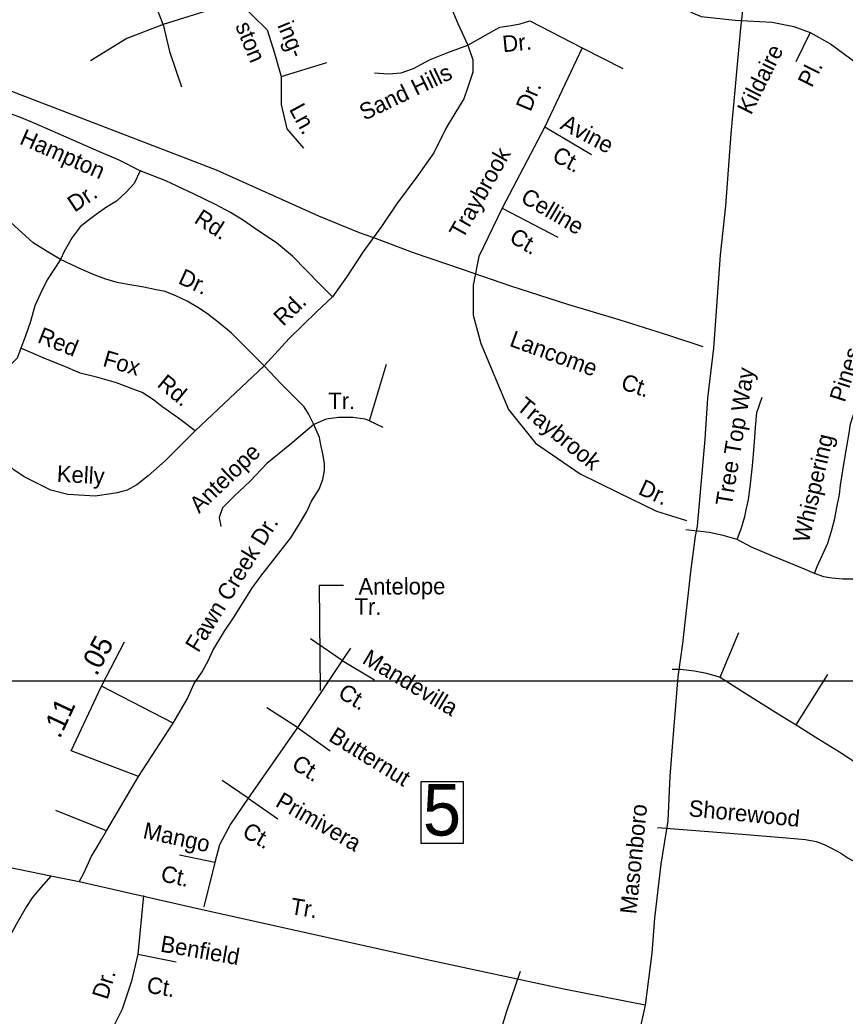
# Model space of a CAD drawing. Extents: x 1945482 to 2853149, y 66427 to 1015778.
# Drawn here: x 2341398 to 2344687, y 153265 to 157233 of the extents above; entities that cross this region are included whole.
import ezdxf

# ---------------------------------------------------------------- set-up
doc = ezdxf.new("R2010")
doc.units = 0
for name, color, linetype in [('Old_Level_10', 7, 'Continuous'), ('Old_Level_11', 7, 'Continuous'), ('Old_Level_31', 7, 'Continuous'), ('Old_Level_32', 7, 'Continuous'), ('Old_Level_35', 7, 'Continuous'), ('Old_Level_63', 7, 'Continuous')]:
    doc.layers.add(name, color=color, linetype=linetype)

msp = doc.modelspace()

# ---------------------------------------------------------------- linework, layer by layer
at = {"layer": 'Old_Level_10'}
msp.add_lwpolyline([(2342688.5, 154979.8), (2342591.2, 154979.8), (2342594.8, 154561.7)], dxfattribs=at)
at = {"layer": 'Old_Level_31'}
msp.add_lwpolyline([(2342998.1, 154198.8), (2343164.4, 154198.8), (2343164.4, 153952.9), (2342998.1, 153952.9)], close=True, dxfattribs=at)
at = {"layer": 'Old_Level_32'}
for points in [[(2344309.2, 157539), (2344270.7, 157199.7), (2344232.2, 156778.6), (2344210.6, 156492.3), (2344188.9, 156295.9), (2344162.5, 155925.4), (2344138.4, 155725.7), (2344128.4, 155563.2), (2344098, 155216.7), (2344089.9, 155176.6), (2344070.7, 155035.1), (2344038.6, 154749.6), (2344020.6, 154616.4), (2344006.2, 154436.7), (2343988.1, 154220.1), (2343980.9, 154043.3), (2343952.1, 153870), (2343926.8, 153655.1), (2343917.2, 153515.5), (2343889.6, 153308.6)], [(2343889.6, 153308.6), (2343565.7, 153372.8), (2343039.8, 153485.1), (2342113.2, 153690.4), (2341634.3, 153799.4), (2341521.8, 153823), (2341308, 153866.4), (2341098.2, 153910.3), (2341029.7, 153923.7), (2340963, 153934.8), (2340619.4, 154012.2), (2340359.7, 154028.2), (2340178.6, 154039.4), (2339839.3, 154055.5), (2339301.6, 154074.7), (2339229.5, 154077.9), (2338943.1, 154093.4), (2338589.8, 154113)], [(2343889.6, 153308.6), (2343857.9, 153165.8), (2343816.2, 153047.1), (2343752.1, 152904.3), (2343535, 152505.6), (2343386.2, 152213.6), (2343300.4, 152065.3), (2343196.1, 151853.5), (2343166, 151804.5), (2343107.6, 151697.1), (2343075.6, 151640.6), (2343054.9, 151582.2), (2343026.7, 151531.3), (2343013.5, 151508.7), (2343013.5, 151503.1), (2343009.7, 151489.9), (2343006, 151471.1), (2342996.6, 151422.1), (2342992.8, 151382.5), (2342995.1, 151254.4)]]:
    msp.add_lwpolyline(points, dxfattribs=at)
at = {"layer": 'Old_Level_35'}
for p, q in [((2342372, 155854.4), (2342096.8, 155596.6)), ((2342791.9, 155635.5), (2342844.8, 155610.8)), ((2344189.4, 154615), (2344262.9, 154792.6)), ((2341722.8, 154579.7), (2341814.5, 154756.2)), ((2344492.3, 154424.9), (2344617.7, 154625.8)), ((2342008.6, 154431.4), (2341722.8, 154579.7)), ((2341871, 154219.5), (2342008.6, 154431.4)), ((2341743, 154003), (2341871, 154219.5)), ((2341743, 154003), (2341541.1, 154083.6))]:
    msp.add_line(p, q, dxfattribs=at)
for points in [[(2343264.7, 158245), (2343247, 158181.4), (2343232.9, 158114.3), (2343116.5, 157725.9), (2343091.8, 157658.8), (2343074.1, 157612.9), (2343053, 157545.8), (2343053, 157499.9), (2343060, 157461), (2343070.6, 157422.2), (2343088.2, 157369.2), (2343112.9, 157291.6), (2343143.4, 157218.8), (2343183.5, 157132.7)], [(2343383.1, 157603.8), (2344079.4, 157261.5), (2344112.7, 157246.4), (2344248.6, 157231.3)], [(2340375.1, 157330.2), (2342180.8, 156636.2), (2342588.1, 156452.2), (2342750.9, 156386.7), (2342807.2, 156365.9)], [(2342135.4, 157266.2), (2341968.6, 157214.2), (2341924.1, 157332.9)], [(2342257.7, 157321.8), (2342324.4, 157252.1), (2342383.7, 157192.7), (2342413.3, 157100), (2342439.3, 157007.3), (2342439.3, 156896), (2342461.5, 156799.6), (2342528.2, 156721.7)], [(2341968.6, 157214.2), (2341824, 157159.4), (2341679.5, 157070.3)], [(2341968.6, 157214.2), (2341994.5, 157107.4), (2342042.7, 156966.5)], [(2343183.5, 157132.7), (2343254.1, 157171.5), (2343310.5, 157203.3), (2343356.4, 157210.3), (2343391.7, 157217.4)], [(2343391.7, 157217.4), (2343431.1, 157229.1), (2343638.7, 157121.5), (2343801.7, 157039.9)], [(2344248.6, 157231.3), (2344396.7, 157223.7), (2344482.2, 157206.5), (2344547.2, 157182.6), (2344629.4, 157138.1), (2344735.4, 157059.3)], [(2344547.2, 157182.6), (2344491.1, 157066.2)], [(2343183.5, 157132.7), (2343202.9, 157074.4), (2343203.4, 157024.4), (2343181.7, 156961.4), (2343167.6, 156919), (2343135.9, 156866.1), (2343097.1, 156802.5), (2343047.7, 156703.6), (2342980.6, 156608.3), (2342899.5, 156498.8), (2342839.5, 156410.5), (2342807.2, 156365.9), (2342765.4, 156308.1), (2342700.3, 156207.5), (2342643.7, 156129.8)], [(2342811.3, 157021.4), (2342867.7, 157017.9), (2342917.1, 157021.4), (2342966.5, 157039.1), (2343030, 157074.4), (2343104.1, 157102.6), (2343183.5, 157132.7)], [(2343638.7, 157121.5), (2343490.4, 156806.3), (2343319.9, 156483.6), (2343227.3, 156290.7), (2343205, 156175.7), (2343205, 156057.1), (2343234.7, 155944.3), (2343345.9, 155681), (2343453.3, 155547.5), (2343631.3, 155425.1), (2343783.2, 155350.9), (2343935.2, 155276.7)], [(2342439.3, 157007.3), (2342620.9, 157062.9)], [(2341878, 156631.2), (2341793.3, 156673.6), (2341712.2, 156708.9), (2341528.7, 156790.1), (2341454.6, 156821.9), (2341398, 156845.9), (2341352.3, 156860.8), (2341313.5, 156867.8), (2341267.6, 156871.4), (2341228.8, 156871.4), (2341158.2, 156853.7)], [(2343490.4, 156806.3), (2343675.7, 156697.2)], [(2341878, 156631.2), (2341853.3, 156581.8), (2341821.6, 156546.5), (2341782.8, 156511.2), (2341743.9, 156486.5), (2341701.6, 156458.2), (2341669.8, 156433.5), (2341638.1, 156408.8), (2341606.3, 156366.4), (2341574.6, 156309.9), (2341560.5, 156278.1)], [(2342643.7, 156129.8), (2342594.3, 156179.3), (2342484.9, 156292.3), (2342421.4, 156345.2), (2342350.8, 156391.1), (2342284.8, 156435.9), (2342237.9, 156465.3), (2342177.9, 156497.1), (2342093.2, 156539.4), (2341980.3, 156592.4), (2341878, 156631.2)], [(2343319.9, 156483.6), (2343542.3, 156367.1)], [(2341560.5, 156278.1), (2341507.5, 156309.9), (2341451.1, 156345.2), (2341377, 156412.3), (2341324.1, 156461.7)], [(2342807.2, 156365.9), (2342966.1, 156306.9), (2343164.7, 156239), (2343353.4, 156174.2), (2343580.4, 156101.2), (2343785, 156039.4), (2343987.5, 155975.2), (2344119.5, 155932.5)], [(2341560.5, 156278.1), (2341507.5, 156196.9), (2341479.3, 156140.4), (2341458.1, 156094.5), (2341440.5, 156031), (2341419.3, 155970.9), (2341401.7, 155925)], [(2342372, 155854.4), (2342294.4, 155932.1), (2342241.4, 155985), (2342195.6, 156023.9), (2342146.2, 156062.7), (2342107.4, 156087.5), (2342065, 156112.2), (2342019.2, 156133.4), (2341976.8, 156151), (2341941.5, 156158.1), (2341892.1, 156168.7), (2341828.6, 156179.3), (2341786.3, 156186.3), (2341740.4, 156200.4), (2341694.5, 156218.1), (2341645.1, 156239.3), (2341560.5, 156278.1)], [(2342643.7, 156129.8), (2342580.2, 156069.8), (2342470.8, 155963.9), (2342372, 155854.4)], [(2341401.7, 155925), (2341387.6, 155886.2), (2341352.3, 155850.9), (2341331.1, 155826.1), (2341292.3, 155773.2), (2341250, 155730.8), (2341207.6, 155688.4), (2341165.3, 155635.5)], [(2342096.8, 155596.6), (2342026.2, 155649.6), (2341963.3, 155693.6), (2341930.9, 155720.2), (2341885.1, 155748.5), (2341839.2, 155766.1), (2341782.8, 155787.3), (2341708.7, 155808.5), (2341638.1, 155826.1), (2341571.1, 155854.4), (2341500.5, 155882.6), (2341401.7, 155925)], [(2342569.6, 155621.3), (2342548.4, 155663.7), (2342530.8, 155692), (2342439, 155783.8), (2342372, 155854.4)], [(2342791.9, 155635.5), (2342858.9, 155861.5)], [(2344564.8, 155028.4), (2344575.6, 155055.3), (2344597.1, 155102), (2344618.6, 155148.6), (2344634.7, 155202.4), (2344645.5, 155247.2), (2344654.4, 155290.3), (2344665.2, 155342.3), (2344668.8, 155379.9), (2344683.1, 155471.4), (2344693.9, 155534.2), (2344702.8, 155586.2), (2344708.2, 155623.9), (2344720.7, 155659.7), (2344733.3, 155695.6), (2344756.6, 155735)], [(2344256.6, 155162.9), (2344274.5, 155209.6), (2344287.1, 155254.4), (2344292.4, 155281.3), (2344301.4, 155322.6), (2344308.6, 155372.8), (2344317.5, 155457.1), (2344324.7, 155534.2), (2344330.1, 155609.5), (2344335.5, 155668.7), (2344357, 155729.7)], [(2342096.8, 155596.6), (2342040.3, 155540.1), (2341976.8, 155476.6), (2341909.8, 155416.5), (2341863.9, 155381.2), (2341825.1, 155360), (2341786.3, 155349.5), (2341743.9, 155342.4), (2341698.1, 155335.3), (2341655.7, 155338.9), (2341588.7, 155342.4), (2341521.7, 155360), (2341465.2, 155388.3), (2341415.8, 155413), (2341373.5, 155441.3), (2341331.1, 155483.6), (2341288.8, 155522.5), (2341239.4, 155571.9), (2341165.3, 155635.5)], [(2342008.6, 154431.4), (2342065, 154526.7), (2342093.2, 154590.3), (2342125, 154636.2), (2342149.7, 154682.1), (2342167.3, 154720.9), (2342213.2, 154798.6), (2342252, 154855.1), (2342322.6, 154968.1), (2342357.9, 155017.5), (2342477.8, 155169.4), (2342513.1, 155225.9), (2342541.3, 155275.3), (2342560.4, 155315.5), (2342590.7, 155363.6), (2342604.9, 155402.4), (2342611.9, 155437.7), (2342611.9, 155466), (2342604.9, 155504.8), (2342597.8, 155540.1), (2342592.2, 155569.9), (2342569.6, 155621.3)], [(2342569.6, 155621.3), (2342474.3, 155540.1), (2342382.6, 155466), (2342315.5, 155395.4), (2342252, 155335.3), (2342206.2, 155289.4), (2342192, 155250.6), (2342199.1, 155215.3)], [(2342791.9, 155635.5), (2342774.2, 155642.5), (2342724.8, 155649.6), (2342668.4, 155649.6), (2342619, 155642.5), (2342569.6, 155621.3)], [(2343935.2, 155276.7), (2344055.3, 155239.4)], [(2344256.6, 155162.9), (2344201, 155179.1), (2344145.5, 155191.6), (2344052, 155202.1)], [(2344564.8, 155028.4), (2344525.4, 155044.6), (2344464.5, 155069.7), (2344392.8, 155100.2), (2344313.9, 155132.4), (2344256.6, 155162.9)], [(2344925, 155030.2), (2344887.4, 155021.3), (2344856.9, 155014.1), (2344813.9, 155008.7), (2344763.7, 155006.9), (2344720.7, 155005.1), (2344677.7, 155005.1), (2344634.7, 155008.7), (2344602.5, 155014.1), (2344564.8, 155028.4)], [(2342682.4, 154681.8), (2342556.4, 154767.1)], [(2342715.8, 154730), (2342682.4, 154681.8), (2342504.5, 154414.8), (2342308.1, 154132.9), (2342237.7, 154029), (2342193.2, 153947.4), (2342174.7, 153877), (2342131.5, 153700)], [(2342682.4, 154681.8), (2342812.1, 154603.9)], [(2343998.1, 154646.9), (2344030.4, 154646.9), (2344087.3, 154640.1), (2344134.6, 154631), (2344189.4, 154615)], [(2341602.8, 154321.9), (2341722.8, 154579.7)], [(2344189.4, 154615), (2344273.6, 154561.2), (2344431.3, 154462.6), (2344492.3, 154424.9)], [(2342504.5, 154414.8), (2342382.2, 154492.6)], [(2344492.3, 154424.9), (2344578.3, 154371.1), (2344664.3, 154317.3), (2344741.3, 154267.1), (2344798.7, 154229.4)], [(2342504.5, 154414.8), (2342634.2, 154322)], [(2341871, 154219.5), (2341602.8, 154321.9)], [(2342308.1, 154132.9), (2342204.3, 154203.3)], [(2342308.1, 154132.9), (2342426.7, 154051.3)], [(2341634.3, 153799.4), (2341654.3, 153837.5), (2341684, 153901.7), (2341705.1, 153937), (2341722.8, 153968.8), (2341743, 154003)], [(2343938.9, 154016.8), (2344260.2, 153991.4), (2344452.9, 153975.1), (2344499, 153970.7), (2344529.3, 153967.9), (2344549.5, 153964.8), (2344559.4, 153963.2), (2344571.7, 153959.8), (2344583.6, 153956), (2344606, 153947), (2344634.8, 153932.1), (2344669.3, 153913.4), (2344702.3, 153892.7), (2344753.3, 153864.9), (2344929.2, 153765.8), (2345152.2, 153646.6), (2345479.6, 153459.4), (2345813.2, 153273.7)], [(2342174.7, 153877), (2342033.8, 153906.6)], [(2341521.8, 153823), (2341472.1, 153766.9), (2341447.1, 153736.1), (2341424.5, 153701), (2341383.4, 153629.5), (2341357.4, 153580.5), (2341327.5, 153523.2), (2341296.4, 153445.9), (2341261.4, 153378.5), (2341189.8, 153261.8), (2341143, 153183.8), (2341060.2, 153044.3), (2341000.1, 152946.1), (2340976.1, 152899.2), (2340970.7, 152884.9), (2340967.3, 152870.6), (2340965.6, 152856.8), (2340966.2, 152842.7), (2340971, 152826.8), (2340977.4, 152815.2), (2340983.6, 152807.3), (2341000.3, 152791.8), (2341025.1, 152770.8)], [(2341891.1, 153745.4), (2341868.5, 153511.3), (2341842.6, 153403.7), (2341805.5, 153292.4), (2341735.1, 153151.5), (2341672.1, 153043.9), (2341538.6, 152869.6), (2341438.6, 152769.5), (2341368.2, 152684.2)], [(2341868.5, 153511.3), (2342020.5, 153481.6)], [(2343391.5, 153442.7), (2343337.8, 153282.7), (2343311.3, 153197.4), (2343300.6, 153161.2), (2343276.7, 153110), (2343245.1, 153044.7), (2343203.1, 152945.3), (2343164.4, 152861.7)]]:
    msp.add_lwpolyline(points, dxfattribs=at)
at = {"layer": 'Old_Level_63'}
msp.add_lwpolyline([(2346064.1, 148689.8), (2332656.4, 148689.8), (2332656.4, 154600.9), (2346064.1, 154600.9)], close=True, dxfattribs=at)

# ---------------------------------------------------------------- texts
at = {"layer": 'Old_Level_10'}
for s, height, rotation, p in [('ston', 65.62, 292.3861, (2342255.6, 157209.9)), ('ing-', 65.62, 292.3861, (2342423.3, 157211.4)), ('Dr.', 65.62, 5.5032, (2343324.1, 157103.8)), ('Kildaire', 65.62, 63.435, (2344312.2, 156851.5)), ('Sand Hills', 65.62, 25.5865, (2342771, 156830.7)), ('Pl.', 65.62, 63.435, (2344554.1, 156960.1)), ('Dr.', 65.62, 67.1665, (2343433.1, 156864.1)), ('Ln.', 65.62, 298.5381, (2342469.7, 156877.4)), ('Avine', 65.62, 331.9276, (2343547.6, 156801.5)), ('Hampton', 65.62, 336.1233, (2341392.7, 156740.6)), ('Traybrook', 65.62, 60.6423, (2343162.9, 156356.6)), ('Ct.', 65.62, 331.9276, (2343514.8, 156674.6)), ('Dr.', 65.62, 33.7103, (2341616.1, 156464.9)), ('Celline', 65.62, 329.5346, (2343389.3, 156510.2)), ('Rd.', 65.62, 326.9559, (2342088.5, 156427.8)), ('Ct.', 65.62, 329.5346, (2343344.1, 156351.4)), ('Dr.', 65.62, 335.2085, (2342025.1, 156184.8)), ('Rd.', 65.62, 44.0829, (2342447.6, 156009.9)), ('Red', 65.62, 338.1833, (2341464.3, 155950.1)), ('Lancome', 65.62, 339.8774, (2343345.6, 155935.4)), ('Fox', 65.62, 344.0426, (2341725, 155855)), ('Pines', 65.62, 72.2974, (2344685.5, 155706.5)), ('Tree Top Way', 65.617, 80.6808, (2344235, 155293.5)), ('Rd.', 65.62, 320.6328, (2341941.1, 155775.5)), ('Ct.', 65.62, 341.5651, (2343789.2, 155763.6)), ('Traybrook', 65.62, 320.779, (2343372.9, 155684.8)), ('Whispering', 65.62, 76.9494, (2344542.1, 155147.1)), ('Antelope', 65.62, 43.8172, (2342112.3, 155264.9)), ('Kelly', 65.62, 356.9849, (2341544.2, 155393.2)), ('Dr.', 65.62, 335.2149, (2343858.6, 155346)), ('Fawn Creek Dr.', 65.617, 58.3693, (2342109.2, 154709.5)), ('Antelope', 65.62, 0.2234, (2342747.7, 154943.6)), ('Tr.', 65.62, 359.4896, (2342731.7, 154863.8)), ('Mandevilla', 65.62, 329.0497, (2342758.4, 154673.2)), ('Ct.', 65.62, 329.0497, (2342661.3, 154537.4)), ('Butternut', 65.62, 328.3102, (2342624.3, 154364.2)), ('Ct.', 65.62, 328.3102, (2342476.4, 154254.1)), ('Primivera', 65.62, 330.0504, (2342412.5, 154103.4)), ('Shorewood', 65.62, 354.4838, (2344061.3, 154061.3)), ('Mango', 65.62, 347.6984, (2341885.2, 153974.3)), ('Ct.', 65.62, 330.0504, (2342279.7, 153983.8)), ('Ct.', 65.62, 347.6984, (2341955.8, 153802.9)), ('Benfield', 65.62, 350.1041, (2341955, 153522.4)), ('Dr.', 65.62, 72.8519, (2341747.1, 153327.6)), ('Ct.', 65.62, 350.1041, (2341900.1, 153359.1))]:
    msp.add_text(s, height=height, rotation=rotation, dxfattribs=at).set_placement(p)
msp.add_text('Tr.', height=65.62, dxfattribs=at).set_placement((2342627.2, 155682.7))
at = {"layer": 'Old_Level_11'}
for s, rotation, p in [('Masonboro', 84.3338, (2343855, 153669.3)), ('Tr.', 350.5194, (2342472.9, 153672))]:
    msp.add_text(s, height=65.62, rotation=rotation, dxfattribs=at).set_placement(p)
at = {"layer": 'Old_Level_31'}
msp.add_text('5', height=205.1, dxfattribs=at).set_placement((2343004, 153984.1))
at = {"layer": 'Old_Level_35'}
for s, rotation, p in [('.05', 62.5436, (2341704, 154616.1)), ('.11', 65.0432, (2341557.3, 154367))]:
    msp.add_text(s, height=82.02, rotation=rotation, dxfattribs=at).set_placement(p)

doc.saveas('drawing.dxf')
